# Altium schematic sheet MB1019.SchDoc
size A3; Revision: C.2
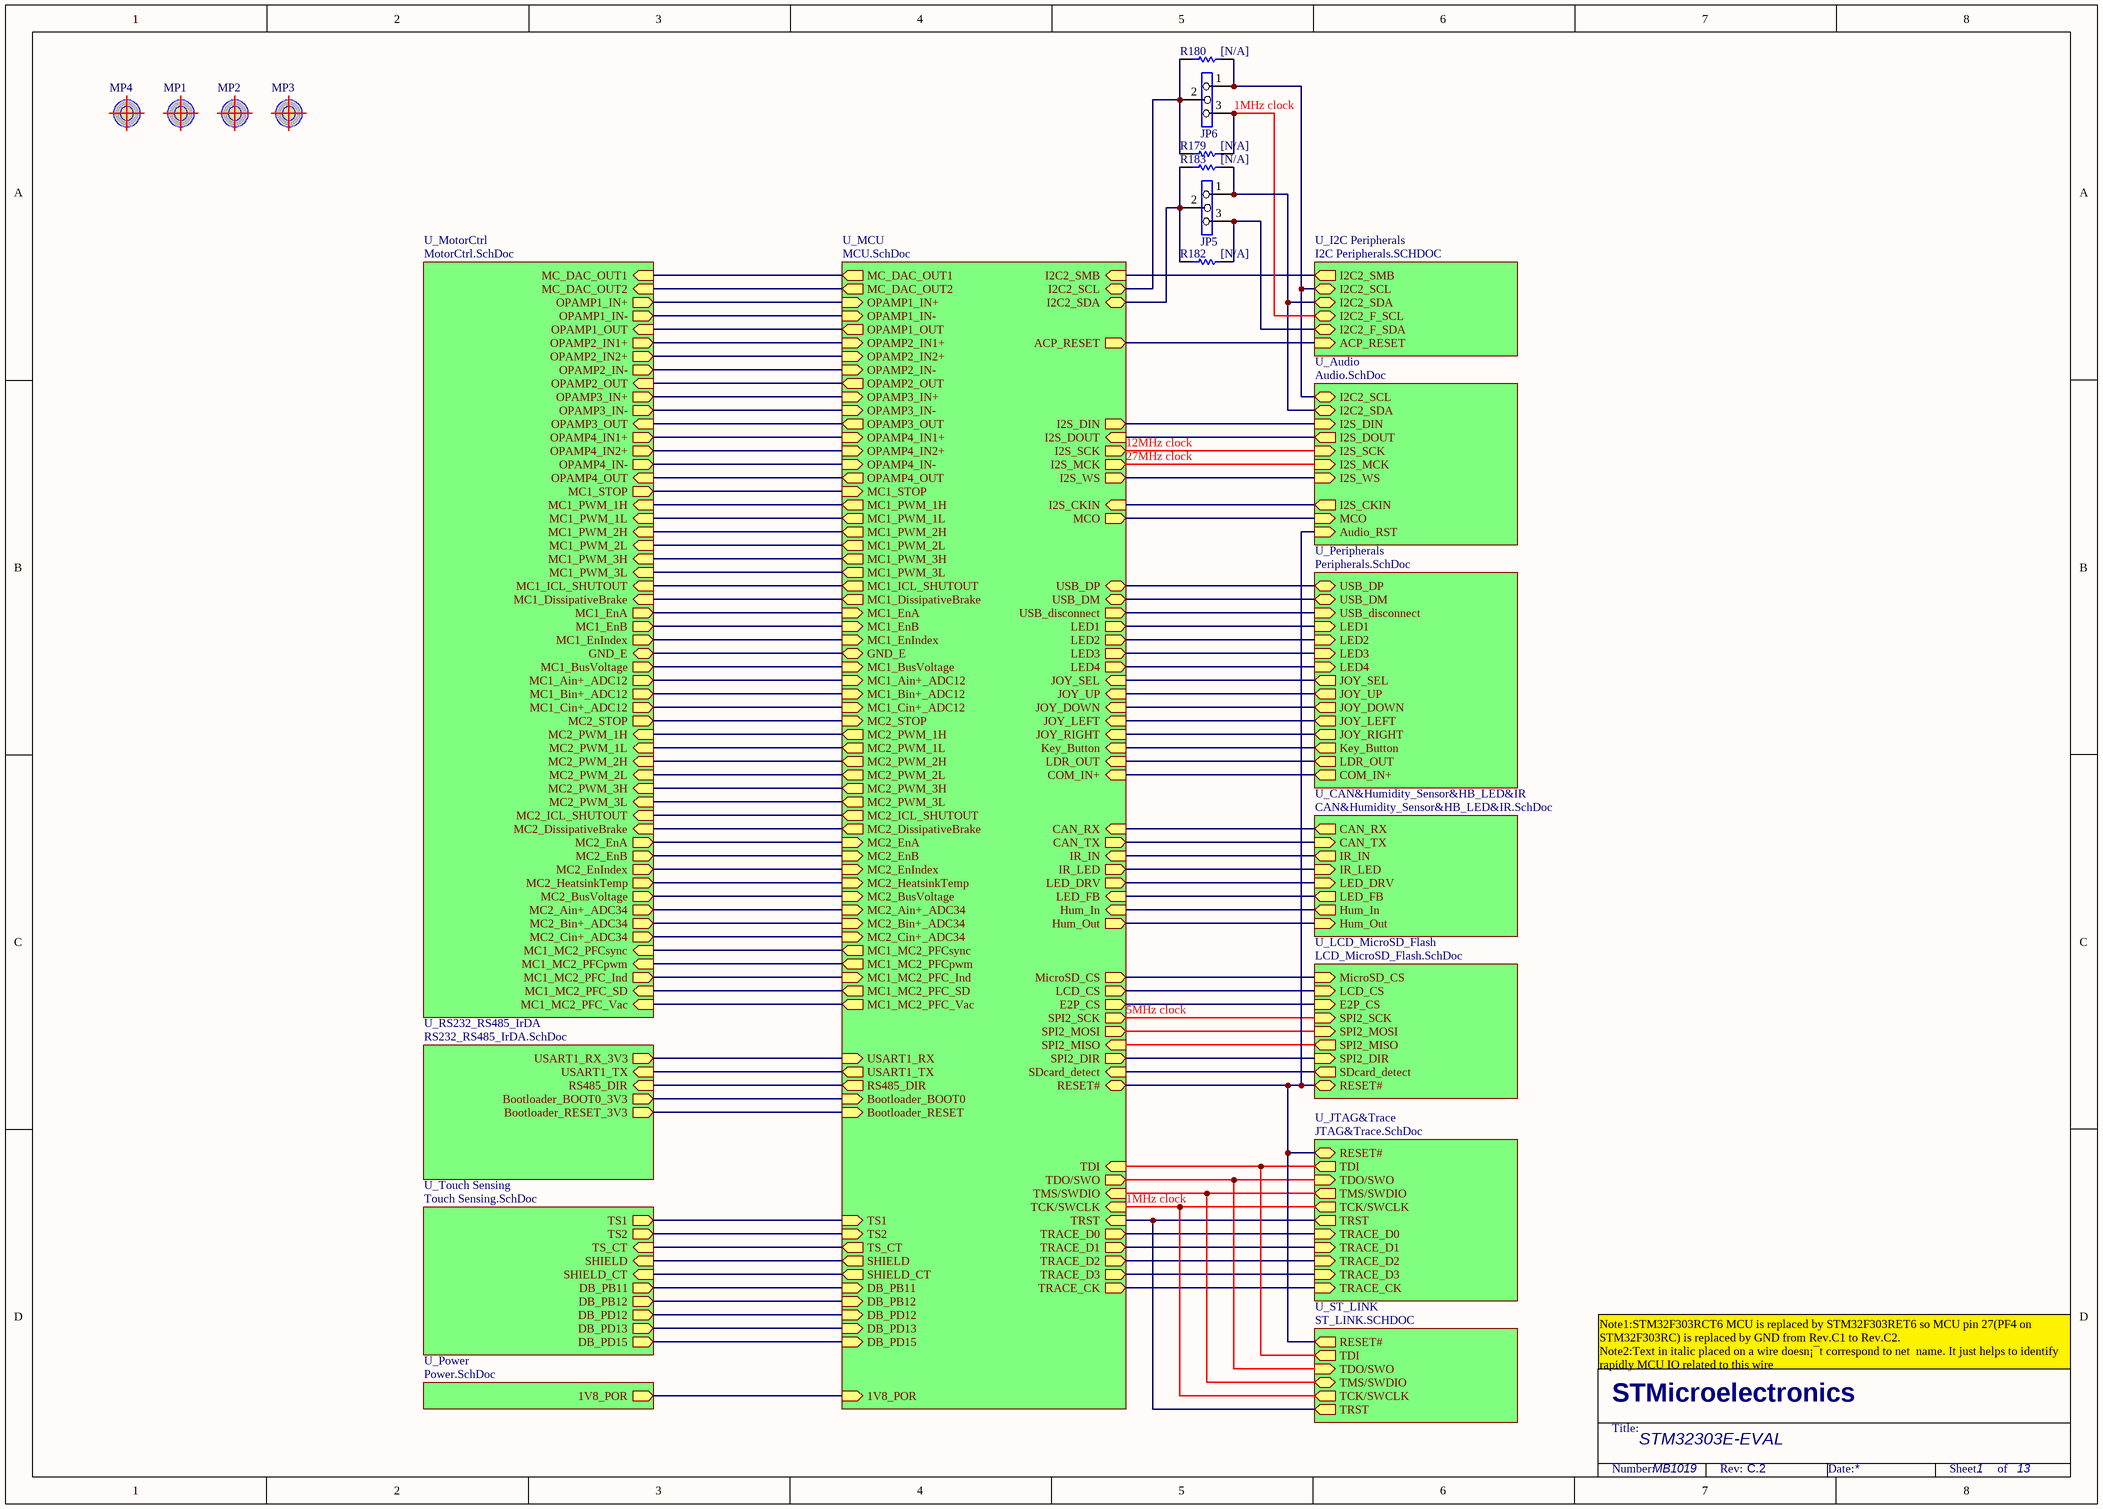
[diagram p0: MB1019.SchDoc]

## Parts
JP5  (no value)  [SIP3]
JP6  (no value)  [SIP3]
MP1  (no value)  [markpoint_1.0]
MP2  (no value)  [markpoint_1.0]
MP3  (no value)  [markpoint_1.0]
MP4  (no value)  [markpoint_1.0]
R179  [N/A]  [0603R]
R180  [N/A]  [0603R]
R182  [N/A]  [0603R]
R183  [N/A]  [0603R]

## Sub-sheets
U_Audio = Audio.SchDoc: I2S_WS (in), I2S_DIN (in), I2S_SCK (in), Audio_RST (in), I2S_MCK (in), MCO (in), I2S_CKIN (out), I2C2_SCL (bidir), I2C2_SDA (bidir), I2S_DOUT (out)
U_CAN&Humidity_Sensor&HB_LED&IR = CAN&Humidity_Sensor&HB_LED&IR.SchDoc: CAN_TX (in), CAN_RX (out), IR_LED (in), IR_IN (out), LED_DRV (in), LED_FB (out), Hum_Out (in), Hum_In (out)
U_I2C Peripherals = I2C Peripherals.SCHDOC: I2C2_SCL (bidir), I2C2_SDA (bidir), I2C2_SMB (out), I2C2_F_SDA (bidir), I2C2_F_SCL (bidir), ACP_RESET (in)
U_JTAG&Trace = JTAG&Trace.SchDoc: TDI (out), RESET# (bidir), TRACE_D3 (in), TRACE_D2 (in), TRACE_D1 (in), TRACE_D0 (in), TRACE_CK (in), TRST (out), TMS/SWDIO (out), TCK/SWCLK (out), TDO/SWO (in)
U_LCD_MicroSD_Flash = LCD_MicroSD_Flash.SchDoc: MicroSD_CS (in), SPI2_SCK (in), SPI2_MOSI (in), LCD_CS (in), SDcard_detect (out), RESET# (bidir), E2P_CS (in), SPI2_MISO (out), SPI2_DIR (in)
U_MCU = MCU.SchDoc: USB_DM (bidir), I2C2_SCL (bidir), I2C2_SDA (bidir), TMS/SWDIO (in), TCK/SWCLK (in), TDI (in), COM_IN+ (in), TDO/SWO (out), TRST (in), IR_IN (in), IR_LED (out), SPI2_MISO (in), SPI2_MOSI (out), RESET# (bidir), LDR_OUT (in), SPI2_SCK (out), USART1_RX (in), USART1_TX (out), LED4 (out), LED3 (out), LED1 (out), LED2 (out), Bootloader_BOOT0 (in), Bootloader_RESET (in), I2C2_SMB (in), USB_DP (bidir), CAN_RX (in), CAN_TX (out), MicroSD_CS (out), TRACE_D0 (out), TRACE_D1 (out), Key_Button (in), JOY_SEL (in), JOY_DOWN (in), JOY_LEFT (in), JOY_UP (in), JOY_RIGHT (in), TRACE_CK (out), E2P_CS (out), LCD_CS (out), TRACE_D2 (out), TRACE_D3 (out), SDcard_detect (in), DB_PD13 (in), DB_PD15 (in), 1V8_POR (in), USB_disconnect (out), MC2_HeatsinkTemp (in), OPAMP1_IN+ (in), OPAMP2_IN1+ (in), OPAMP3_IN+ (in), OPAMP3_OUT (out), OPAMP3_IN- (in), MC2_EnA (in), MC2_STOP (in), MC2_EnIndex (in), OPAMP4_IN- (in), OPAMP4_OUT (out), OPAMP4_IN1+ (in), MC1_Cin+_ADC12 (in), MC1_Ain+_ADC12 (in), MC1_Bin+_ADC12 (in), MC2_PWM_1H (out), MC2_PWM_2H (out), MC2_PWM_3H (out), MC2_PWM_1L (out), MC2_PWM_2L (out), MC2_PWM_3L (out), MC1_MC2_PFC_SD (out), MC1_EnA (in), MC1_EnB (in), MC1_EnIndex (in), MC1_MC2_PFC_Ind (in), MC2_EnB (in), MC1_MC2_PFCsync (out), MC1_MC2_PFCpwm (out), MC1_ICL_SHUTOUT (out), MC1_DissipativeBrake (out), MC1_PWM_1H (out), MC1_PWM_2H (out), MC1_PWM_3H (out), MC1_PWM_1L (out), MC1_PWM_2L (out), MC1_PWM_3L (out), LED_DRV (out), MC1_STOP (in), LED_FB (in), GND_E (bidir), MC2_ICL_SHUTOUT (out), MC2_DissipativeBrake (out), MC1_MC2_PFC_Vac (out), MC2_BusVoltage (in), MC_DAC_OUT1 (out), MC_DAC_OUT2 (out), OPAMP1_OUT (out), OPAMP1_IN- (in), OPAMP2_OUT (out), OPAMP4_IN2+ (in), OPAMP2_IN2+ (in), MC1_BusVoltage (in), RS485_DIR (out), Hum_Out (out), TS2 (in), Hum_In (in), I2S_WS (out), SHIELD (out), OPAMP2_IN- (in), MC2_Cin+_ADC34 (in), MC2_Ain+_ADC34 (in), MC2_Bin+_ADC34 (in), TS_CT (out), TS1 (in), DB_PB12 (in), SHIELD_CT (out), DB_PD12 (in), DB_PB11 (in), ACP_RESET (out), I2S_CKIN (in), MCO (out), I2S_DIN (out), I2S_SCK (out), I2S_MCK (out), I2S_DOUT (in), SPI2_DIR (out)
U_MotorCtrl = MotorCtrl.SchDoc: MC1_STOP (out), MC1_MC2_PFCsync (in), MC1_ICL_SHUTOUT (in), MC1_DissipativeBrake (in), MC1_MC2_PFCpwm (in), MC1_EnA (out), MC1_EnB (out), GND_E (bidir), MC1_BusVoltage (out), MC1_EnIndex (out), MC1_PWM_1H (in), MC1_PWM_2H (in), MC1_PWM_3H (in), MC1_PWM_1L (in), MC1_PWM_2L (in), MC1_PWM_3L (in), MC1_MC2_PFC_Ind (out), MC1_MC2_PFC_Vac (in), MC1_MC2_PFC_SD (in), MC2_STOP (out), MC2_ICL_SHUTOUT (in), MC2_DissipativeBrake (in), MC2_EnA (out), MC2_EnB (out), MC2_HeatsinkTemp (out), MC2_BusVoltage (out), MC2_EnIndex (out), MC2_PWM_1H (in), MC2_PWM_2H (in), MC2_PWM_3H (in), MC2_PWM_1L (in), MC2_PWM_2L (in), MC2_PWM_3L (in), OPAMP1_IN+ (out), OPAMP1_IN- (out), OPAMP1_OUT (in), MC1_Ain+_ADC12 (out), MC_DAC_OUT2 (in), MC_DAC_OUT1 (in), OPAMP2_IN1+ (out), OPAMP2_IN- (out), OPAMP2_OUT (in), OPAMP2_IN2+ (out), OPAMP4_IN1+ (out), OPAMP4_IN- (out), OPAMP4_OUT (in), OPAMP4_IN2+ (out), OPAMP3_IN+ (out), OPAMP3_IN- (out), OPAMP3_OUT (in), MC1_Bin+_ADC12 (out), MC1_Cin+_ADC12 (out), MC2_Cin+_ADC34 (out), MC2_Bin+_ADC34 (out), MC2_Ain+_ADC34 (out)
U_Peripherals = Peripherals.SchDoc: JOY_SEL (out), JOY_DOWN (out), JOY_LEFT (out), JOY_RIGHT (out), JOY_UP (out), USB_DM (bidir), USB_DP (bidir), Key_Button (out), USB_disconnect (in), LDR_OUT (out), COM_IN+ (out), LED4 (in), LED3 (in), LED1 (in), LED2 (in)
U_Power = Power.SchDoc: 1V8_POR (out)
U_RS232_RS485_IrDA = RS232_RS485_IrDA.SchDoc: USART1_RX_3V3 (out), RS485_DIR (in), Bootloader_BOOT0_3V3 (out), Bootloader_RESET_3V3 (out), USART1_TX (in)
U_ST_LINK = ST_LINK.SCHDOC: TDI (out), TRST (out), TMS/SWDIO (bidir), TCK/SWCLK (out), TDO/SWO (in), RESET# (out)
U_Touch Sensing = Touch Sensing.SchDoc: TS1 (out), TS2 (out), SHIELD (in), SHIELD_CT (in), TS_CT (in), DB_PD13 (out), DB_PD15 (out), DB_PD12 (out), DB_PB11 (out), DB_PB12 (out)

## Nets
NetJP5_1: JP5.1 R183.1 ; sheet U_Audio/I2C2_SDA, sheet U_I2C Peripherals/I2C2_SDA
NetJP5_2: JP5.2 R182.2 R183.2 ; sheet U_MCU/I2C2_SDA
NetJP5_3: JP5.3 R182.1 ; sheet U_I2C Peripherals/I2C2_F_SDA
NetJP6_1: JP6.1 R180.1 ; sheet U_Audio/I2C2_SCL, sheet U_I2C Peripherals/I2C2_SCL
NetJP6_2: JP6.2 R179.2 R180.2 ; sheet U_MCU/I2C2_SCL
NetJP6_3: JP6.3 R179.1 ; sheet U_I2C Peripherals/I2C2_F_SCL
(unnamed): sheet U_MCU/USB_DM, sheet U_Peripherals/USB_DM
(unnamed): sheet U_MCU/TMS/SWDIO, sheet U_JTAG&Trace/TMS/SWDIO, sheet U_ST_LINK/TMS/SWDIO  [a separate net that carries the same name]
(unnamed): sheet U_MCU/TCK/SWCLK, sheet U_JTAG&Trace/TCK/SWCLK, sheet U_ST_LINK/TCK/SWCLK  [a separate net that carries the same name]
(unnamed): sheet U_MCU/TDI, sheet U_JTAG&Trace/TDI, sheet U_ST_LINK/TDI  [a separate net that carries the same name]
(unnamed): sheet U_MCU/COM_IN+, sheet U_Peripherals/COM_IN+  [a separate net that carries the same name]
(unnamed): sheet U_MCU/TDO/SWO, sheet U_JTAG&Trace/TDO/SWO, sheet U_ST_LINK/TDO/SWO  [a separate net that carries the same name]
(unnamed): sheet U_MCU/TRST, sheet U_JTAG&Trace/TRST, sheet U_ST_LINK/TRST  [a separate net that carries the same name]
(unnamed): sheet U_MCU/IR_IN, sheet U_CAN&Humidity_Sensor&HB_LED&IR/IR_IN  [a separate net that carries the same name]
(unnamed): sheet U_MCU/IR_LED, sheet U_CAN&Humidity_Sensor&HB_LED&IR/IR_LED  [a separate net that carries the same name]
(unnamed): sheet U_MCU/SPI2_MISO, sheet U_LCD_MicroSD_Flash/SPI2_MISO  [a separate net that carries the same name]
(unnamed): sheet U_MCU/SPI2_MOSI, sheet U_LCD_MicroSD_Flash/SPI2_MOSI  [a separate net that carries the same name]
(unnamed): sheet U_MCU/RESET#, sheet U_JTAG&Trace/RESET#, sheet U_ST_LINK/RESET#, sheet U_Audio/Audio_RST, sheet U_LCD_MicroSD_Flash/RESET#  [a separate net that carries the same name]
(unnamed): sheet U_MCU/LDR_OUT, sheet U_Peripherals/LDR_OUT  [a separate net that carries the same name]
(unnamed): sheet U_MCU/SPI2_SCK, sheet U_LCD_MicroSD_Flash/SPI2_SCK  [a separate net that carries the same name]
(unnamed): sheet U_MCU/USART1_RX, sheet U_RS232_RS485_IrDA/USART1_RX_3V3  [a separate net that carries the same name]
(unnamed): sheet U_MCU/USART1_TX, sheet U_RS232_RS485_IrDA/USART1_TX  [a separate net that carries the same name]
(unnamed): sheet U_MCU/LED4, sheet U_Peripherals/LED4  [a separate net that carries the same name]
(unnamed): sheet U_MCU/LED3, sheet U_Peripherals/LED3  [a separate net that carries the same name]
(unnamed): sheet U_MCU/LED1, sheet U_Peripherals/LED1  [a separate net that carries the same name]
(unnamed): sheet U_MCU/LED2, sheet U_Peripherals/LED2  [a separate net that carries the same name]
(unnamed): sheet U_MCU/Bootloader_BOOT0, sheet U_RS232_RS485_IrDA/Bootloader_BOOT0_3V3  [a separate net that carries the same name]
(unnamed): sheet U_MCU/Bootloader_RESET, sheet U_RS232_RS485_IrDA/Bootloader_RESET_3V3  [a separate net that carries the same name]
(unnamed): sheet U_MCU/I2C2_SMB, sheet U_I2C Peripherals/I2C2_SMB  [a separate net that carries the same name]
(unnamed): sheet U_MCU/USB_DP, sheet U_Peripherals/USB_DP  [a separate net that carries the same name]
(unnamed): sheet U_MCU/CAN_RX, sheet U_CAN&Humidity_Sensor&HB_LED&IR/CAN_RX  [a separate net that carries the same name]
(unnamed): sheet U_MCU/CAN_TX, sheet U_CAN&Humidity_Sensor&HB_LED&IR/CAN_TX  [a separate net that carries the same name]
(unnamed): sheet U_MCU/MicroSD_CS, sheet U_LCD_MicroSD_Flash/MicroSD_CS  [a separate net that carries the same name]
(unnamed): sheet U_MCU/TRACE_D0, sheet U_JTAG&Trace/TRACE_D0  [a separate net that carries the same name]
(unnamed): sheet U_MCU/TRACE_D1, sheet U_JTAG&Trace/TRACE_D1  [a separate net that carries the same name]
(unnamed): sheet U_MCU/Key_Button, sheet U_Peripherals/Key_Button  [a separate net that carries the same name]
(unnamed): sheet U_MCU/JOY_SEL, sheet U_Peripherals/JOY_SEL  [a separate net that carries the same name]
(unnamed): sheet U_MCU/JOY_DOWN, sheet U_Peripherals/JOY_DOWN  [a separate net that carries the same name]
(unnamed): sheet U_MCU/JOY_LEFT, sheet U_Peripherals/JOY_LEFT  [a separate net that carries the same name]
(unnamed): sheet U_MCU/JOY_UP, sheet U_Peripherals/JOY_UP  [a separate net that carries the same name]
(unnamed): sheet U_MCU/JOY_RIGHT, sheet U_Peripherals/JOY_RIGHT  [a separate net that carries the same name]
(unnamed): sheet U_MCU/TRACE_CK, sheet U_JTAG&Trace/TRACE_CK  [a separate net that carries the same name]
(unnamed): sheet U_MCU/E2P_CS, sheet U_LCD_MicroSD_Flash/E2P_CS  [a separate net that carries the same name]
(unnamed): sheet U_MCU/LCD_CS, sheet U_LCD_MicroSD_Flash/LCD_CS  [a separate net that carries the same name]
(unnamed): sheet U_MCU/TRACE_D2, sheet U_JTAG&Trace/TRACE_D2  [a separate net that carries the same name]
(unnamed): sheet U_MCU/TRACE_D3, sheet U_JTAG&Trace/TRACE_D3  [a separate net that carries the same name]
(unnamed): sheet U_MCU/SDcard_detect, sheet U_LCD_MicroSD_Flash/SDcard_detect  [a separate net that carries the same name]
(unnamed): sheet U_MCU/DB_PD13, sheet U_Touch Sensing/DB_PD13  [a separate net that carries the same name]
(unnamed): sheet U_MCU/DB_PD15, sheet U_Touch Sensing/DB_PD15  [a separate net that carries the same name]
(unnamed): sheet U_MCU/1V8_POR, sheet U_Power/1V8_POR  [a separate net that carries the same name]
(unnamed): sheet U_MCU/USB_disconnect, sheet U_Peripherals/USB_disconnect  [a separate net that carries the same name]
(unnamed): sheet U_MCU/MC2_HeatsinkTemp, sheet U_MotorCtrl/MC2_HeatsinkTemp  [a separate net that carries the same name]
(unnamed): sheet U_MCU/OPAMP1_IN+, sheet U_MotorCtrl/OPAMP1_IN+  [a separate net that carries the same name]
(unnamed): sheet U_MCU/OPAMP2_IN1+, sheet U_MotorCtrl/OPAMP2_IN1+  [a separate net that carries the same name]
(unnamed): sheet U_MCU/OPAMP3_IN+, sheet U_MotorCtrl/OPAMP3_IN+  [a separate net that carries the same name]
(unnamed): sheet U_MCU/OPAMP3_OUT, sheet U_MotorCtrl/OPAMP3_OUT  [a separate net that carries the same name]
(unnamed): sheet U_MCU/OPAMP3_IN-, sheet U_MotorCtrl/OPAMP3_IN-  [a separate net that carries the same name]
(unnamed): sheet U_MCU/MC2_EnA, sheet U_MotorCtrl/MC2_EnA  [a separate net that carries the same name]
(unnamed): sheet U_MCU/MC2_STOP, sheet U_MotorCtrl/MC2_STOP  [a separate net that carries the same name]
(unnamed): sheet U_MCU/MC2_EnIndex, sheet U_MotorCtrl/MC2_EnIndex  [a separate net that carries the same name]
(unnamed): sheet U_MCU/OPAMP4_IN-, sheet U_MotorCtrl/OPAMP4_IN-  [a separate net that carries the same name]
(unnamed): sheet U_MCU/OPAMP4_OUT, sheet U_MotorCtrl/OPAMP4_OUT  [a separate net that carries the same name]
(unnamed): sheet U_MCU/OPAMP4_IN1+, sheet U_MotorCtrl/OPAMP4_IN1+  [a separate net that carries the same name]
(unnamed): sheet U_MCU/MC1_Cin+_ADC12, sheet U_MotorCtrl/MC1_Cin+_ADC12  [a separate net that carries the same name]
(unnamed): sheet U_MCU/MC1_Ain+_ADC12, sheet U_MotorCtrl/MC1_Ain+_ADC12  [a separate net that carries the same name]
(unnamed): sheet U_MCU/MC1_Bin+_ADC12, sheet U_MotorCtrl/MC1_Bin+_ADC12  [a separate net that carries the same name]
(unnamed): sheet U_MCU/MC2_PWM_1H, sheet U_MotorCtrl/MC2_PWM_1H  [a separate net that carries the same name]
(unnamed): sheet U_MCU/MC2_PWM_2H, sheet U_MotorCtrl/MC2_PWM_2H  [a separate net that carries the same name]
(unnamed): sheet U_MCU/MC2_PWM_3H, sheet U_MotorCtrl/MC2_PWM_3H  [a separate net that carries the same name]
(unnamed): sheet U_MCU/MC2_PWM_1L, sheet U_MotorCtrl/MC2_PWM_1L  [a separate net that carries the same name]
(unnamed): sheet U_MCU/MC2_PWM_2L, sheet U_MotorCtrl/MC2_PWM_2L  [a separate net that carries the same name]
(unnamed): sheet U_MCU/MC2_PWM_3L, sheet U_MotorCtrl/MC2_PWM_3L  [a separate net that carries the same name]
(unnamed): sheet U_MCU/MC1_MC2_PFC_SD, sheet U_MotorCtrl/MC1_MC2_PFC_SD  [a separate net that carries the same name]
(unnamed): sheet U_MCU/MC1_EnA, sheet U_MotorCtrl/MC1_EnA  [a separate net that carries the same name]
(unnamed): sheet U_MCU/MC1_EnB, sheet U_MotorCtrl/MC1_EnB  [a separate net that carries the same name]
(unnamed): sheet U_MCU/MC1_EnIndex, sheet U_MotorCtrl/MC1_EnIndex  [a separate net that carries the same name]
(unnamed): sheet U_MCU/MC1_MC2_PFC_Ind, sheet U_MotorCtrl/MC1_MC2_PFC_Ind  [a separate net that carries the same name]
(unnamed): sheet U_MCU/MC2_EnB, sheet U_MotorCtrl/MC2_EnB  [a separate net that carries the same name]
(unnamed): sheet U_MCU/MC1_MC2_PFCsync, sheet U_MotorCtrl/MC1_MC2_PFCsync  [a separate net that carries the same name]
(unnamed): sheet U_MCU/MC1_MC2_PFCpwm, sheet U_MotorCtrl/MC1_MC2_PFCpwm  [a separate net that carries the same name]
(unnamed): sheet U_MCU/MC1_ICL_SHUTOUT, sheet U_MotorCtrl/MC1_ICL_SHUTOUT  [a separate net that carries the same name]
(unnamed): sheet U_MCU/MC1_DissipativeBrake, sheet U_MotorCtrl/MC1_DissipativeBrake  [a separate net that carries the same name]
(unnamed): sheet U_MCU/MC1_PWM_1H, sheet U_MotorCtrl/MC1_PWM_1H  [a separate net that carries the same name]
(unnamed): sheet U_MCU/MC1_PWM_2H, sheet U_MotorCtrl/MC1_PWM_2H  [a separate net that carries the same name]
(unnamed): sheet U_MCU/MC1_PWM_3H, sheet U_MotorCtrl/MC1_PWM_3H  [a separate net that carries the same name]
(unnamed): sheet U_MCU/MC1_PWM_1L, sheet U_MotorCtrl/MC1_PWM_1L  [a separate net that carries the same name]
(unnamed): sheet U_MCU/MC1_PWM_2L, sheet U_MotorCtrl/MC1_PWM_2L  [a separate net that carries the same name]
(unnamed): sheet U_MCU/MC1_PWM_3L, sheet U_MotorCtrl/MC1_PWM_3L  [a separate net that carries the same name]
(unnamed): sheet U_MCU/LED_DRV, sheet U_CAN&Humidity_Sensor&HB_LED&IR/LED_DRV  [a separate net that carries the same name]
(unnamed): sheet U_MCU/MC1_STOP, sheet U_MotorCtrl/MC1_STOP  [a separate net that carries the same name]
(unnamed): sheet U_MCU/LED_FB, sheet U_CAN&Humidity_Sensor&HB_LED&IR/LED_FB  [a separate net that carries the same name]
(unnamed): sheet U_MCU/GND_E, sheet U_MotorCtrl/GND_E  [a separate net that carries the same name]
(unnamed): sheet U_MCU/MC2_ICL_SHUTOUT, sheet U_MotorCtrl/MC2_ICL_SHUTOUT  [a separate net that carries the same name]
(unnamed): sheet U_MCU/MC2_DissipativeBrake, sheet U_MotorCtrl/MC2_DissipativeBrake  [a separate net that carries the same name]
(unnamed): sheet U_MCU/MC1_MC2_PFC_Vac, sheet U_MotorCtrl/MC1_MC2_PFC_Vac  [a separate net that carries the same name]
(unnamed): sheet U_MCU/MC2_BusVoltage, sheet U_MotorCtrl/MC2_BusVoltage  [a separate net that carries the same name]
(unnamed): sheet U_MCU/MC_DAC_OUT1, sheet U_MotorCtrl/MC_DAC_OUT1  [a separate net that carries the same name]
(unnamed): sheet U_MCU/MC_DAC_OUT2, sheet U_MotorCtrl/MC_DAC_OUT2  [a separate net that carries the same name]
(unnamed): sheet U_MCU/OPAMP1_OUT, sheet U_MotorCtrl/OPAMP1_OUT  [a separate net that carries the same name]
(unnamed): sheet U_MCU/OPAMP1_IN-, sheet U_MotorCtrl/OPAMP1_IN-  [a separate net that carries the same name]
(unnamed): sheet U_MCU/OPAMP2_OUT, sheet U_MotorCtrl/OPAMP2_OUT  [a separate net that carries the same name]
(unnamed): sheet U_MCU/OPAMP4_IN2+, sheet U_MotorCtrl/OPAMP4_IN2+  [a separate net that carries the same name]
(unnamed): sheet U_MCU/OPAMP2_IN2+, sheet U_MotorCtrl/OPAMP2_IN2+  [a separate net that carries the same name]
(unnamed): sheet U_MCU/MC1_BusVoltage, sheet U_MotorCtrl/MC1_BusVoltage  [a separate net that carries the same name]
(unnamed): sheet U_MCU/RS485_DIR, sheet U_RS232_RS485_IrDA/RS485_DIR  [a separate net that carries the same name]
(unnamed): sheet U_MCU/Hum_Out, sheet U_CAN&Humidity_Sensor&HB_LED&IR/Hum_Out  [a separate net that carries the same name]
(unnamed): sheet U_MCU/TS2, sheet U_Touch Sensing/TS2  [a separate net that carries the same name]
(unnamed): sheet U_MCU/Hum_In, sheet U_CAN&Humidity_Sensor&HB_LED&IR/Hum_In  [a separate net that carries the same name]
(unnamed): sheet U_MCU/I2S_WS, sheet U_Audio/I2S_WS  [a separate net that carries the same name]
(unnamed): sheet U_MCU/SHIELD, sheet U_Touch Sensing/SHIELD  [a separate net that carries the same name]
(unnamed): sheet U_MCU/OPAMP2_IN-, sheet U_MotorCtrl/OPAMP2_IN-  [a separate net that carries the same name]
(unnamed): sheet U_MCU/MC2_Cin+_ADC34, sheet U_MotorCtrl/MC2_Cin+_ADC34  [a separate net that carries the same name]
(unnamed): sheet U_MCU/MC2_Ain+_ADC34, sheet U_MotorCtrl/MC2_Ain+_ADC34  [a separate net that carries the same name]
(unnamed): sheet U_MCU/MC2_Bin+_ADC34, sheet U_MotorCtrl/MC2_Bin+_ADC34  [a separate net that carries the same name]
(unnamed): sheet U_MCU/TS_CT, sheet U_Touch Sensing/TS_CT  [a separate net that carries the same name]
(unnamed): sheet U_MCU/TS1, sheet U_Touch Sensing/TS1  [a separate net that carries the same name]
(unnamed): sheet U_MCU/DB_PB12, sheet U_Touch Sensing/DB_PB12  [a separate net that carries the same name]
(unnamed): sheet U_MCU/SHIELD_CT, sheet U_Touch Sensing/SHIELD_CT  [a separate net that carries the same name]
(unnamed): sheet U_MCU/DB_PD12, sheet U_Touch Sensing/DB_PD12  [a separate net that carries the same name]
(unnamed): sheet U_MCU/DB_PB11, sheet U_Touch Sensing/DB_PB11  [a separate net that carries the same name]
(unnamed): sheet U_MCU/ACP_RESET, sheet U_I2C Peripherals/ACP_RESET  [a separate net that carries the same name]
(unnamed): sheet U_MCU/I2S_CKIN, sheet U_Audio/I2S_CKIN  [a separate net that carries the same name]
(unnamed): sheet U_MCU/MCO, sheet U_Audio/MCO  [a separate net that carries the same name]
(unnamed): sheet U_MCU/I2S_DIN, sheet U_Audio/I2S_DIN  [a separate net that carries the same name]
(unnamed): sheet U_MCU/I2S_SCK, sheet U_Audio/I2S_SCK  [a separate net that carries the same name]
(unnamed): sheet U_MCU/I2S_MCK, sheet U_Audio/I2S_MCK  [a separate net that carries the same name]
(unnamed): sheet U_MCU/I2S_DOUT, sheet U_Audio/I2S_DOUT  [a separate net that carries the same name]
(unnamed): sheet U_MCU/SPI2_DIR, sheet U_LCD_MicroSD_Flash/SPI2_DIR  [a separate net that carries the same name]

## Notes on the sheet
- (near JP6) 1MHz clock
- 12MHz clock
- 27MHz clock
- 5MHz clock
- 1MHz clock
- Note1:STM32F303RCT6 MCU is replaced by STM32F303RET6 so MCU pin 27(PF4 on STM32F303RC) is replaced by GND from Rev.C1 to Rev.C2.
  Note2:Text in italic placed on a wire doesn¡¯t correspond to net  name. It just helps to identify rapidly MCU IO related to this wire
- STM32303E-EVAL
- MB1019
- 1
- 13

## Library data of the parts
JP5 JP6 = Jumper3
MP1-MP4 = MARKPOINT
R179 R180 R182 R183 = Res1: Resistor; Value: 1K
